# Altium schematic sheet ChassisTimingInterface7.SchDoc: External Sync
size B; Author: M. Pirello; Organization: LIGO Laboratory; Address1: California Institute of Technology; Address2: Massachusetts Institute of Technology; Address3: National Science Foundation; Address4: Australia 2086; DocumentNumber: 8; SheetNumber: 8; SheetTotal: 12; Size: B
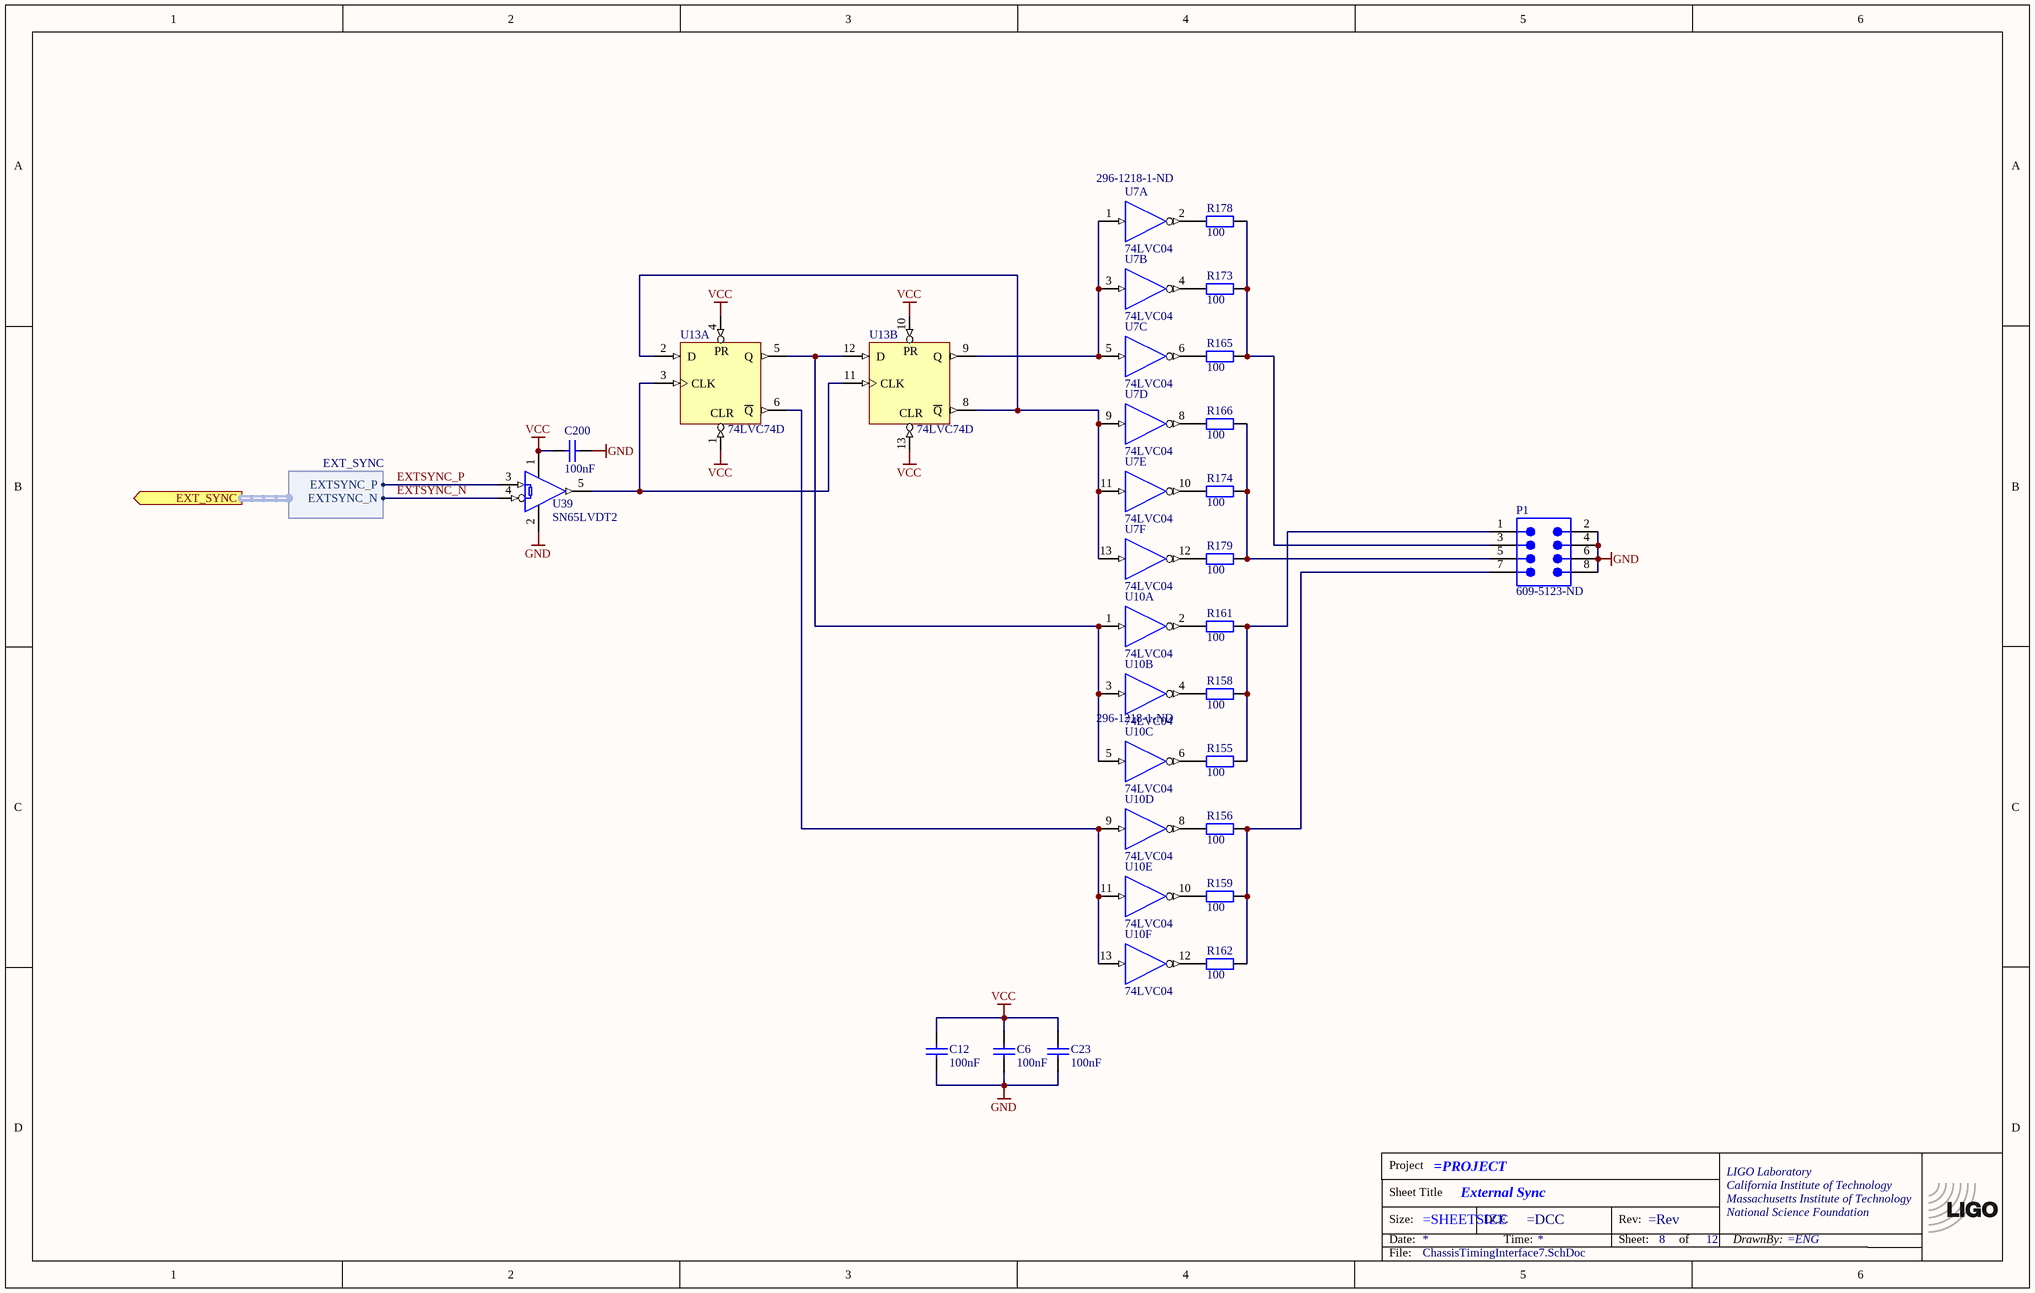
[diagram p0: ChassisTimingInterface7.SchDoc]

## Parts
*?  TitleBlock  (value not drawn)  (graphical)
?  (no value)  (no BOM)
C6  100nF  [CC1005-0402]
C12  100nF  [CC1005-0402]
C23  100nF  [CC1005-0402]
C200  100nF  [CC1005-0402]
P1  609-5123-ND  [9181089621]
R155  100  [CR1608-0603]
R156  100  [CR1608-0603]
R158  100  [CR1608-0603]
R159  100  [CR1608-0603]
R161  100  [CR1608-0603]
R162  100  [CR1608-0603]
R165  100  [CR1608-0603]
R166  100  [CR1608-0603]
R173  100  [CR1608-0603]
R174  100  [CR1608-0603]
R178  100  [CR1608-0603]
R179  100  [CR1608-0603]
U7  74LVC04  Supplier Part Number 1: 296-1218-1-ND  [TSSOP14]  (parts A,B,C,D,E,F of 6)
U10  74LVC04  [TSSOP14]  (parts A,B,C,D,E,F of 6)
U13  74LVC74D  [TSSOP14]  (parts A,B of 2)
U39  SN65LVDT2  [SO-G5/E2.4]

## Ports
EXT_SYNC (out, harness EXT_SYNC)

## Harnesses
EXT_SYNC: EXTSYNC_N, EXTSYNC_P

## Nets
GND: C6.2 C12.2 C23.2 C200.1 P1.2 P1.4 P1.6 P1.8 U7.7(GND) U10.7(GND) U13.7(GND) U39.2(GND)
VCC: C6.1 C12.1 C23.1 C200.2 U7.14(VCC) U10.14(VCC) U13.1(CLR) U13.4(PR) U13.10(PR) U13.13(CLR) U13.14(VCC) U39.1(VCC)
EXTSYNC_N: U39.4(B) ; port EXT_SYNC.EXTSYNC_N
EXTSYNC_P: U39.3(A) ; port EXT_SYNC.EXTSYNC_P
NetP1_1: P1.1 R155.2 R158.2 R161.2
NetP1_3: P1.3 R165.2 R173.2 R178.2
NetP1_5: P1.5 R166.2 R174.2 R179.2
NetP1_7: P1.7 R156.2 R159.2 R162.2
NetR155_1: R155.1 U10.6(Y)
NetR156_1: R156.1 U10.8(Y)
NetR158_1: R158.1 U10.4(Y)
NetR159_1: R159.1 U10.10(Y)
NetR161_1: R161.1 U10.2(Y)
NetR162_1: R162.1 U10.12(Y)
NetR165_1: R165.1 U7.6(Y)
NetR166_1: R166.1 U7.8(Y)
NetR173_1: R173.1 U7.4(Y)
NetR174_1: R174.1 U7.10(Y)
NetR178_1: R178.1 U7.2(Y)
NetR179_1: R179.1 U7.12(Y)
NetU7_1: U7.1(A) U7.3(A) U7.5(A) U13.9(Q)
NetU7_9: U7.9(A) U7.11(A) U7.13(A) U13.2(D) U13.8(~{Q})
NetU10_1: U10.1(A) U10.3(A) U10.5(A) U13.5(Q) U13.12(D)
NetU10_9: U10.9(A) U10.11(A) U10.13(A) U13.6(~{Q})
NetU13_3: U13.3(CLK) U13.11(CLK) U39.5(R)

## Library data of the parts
? = LIGO_logo: LIGO logo
C6 C12 C23 C200 = ChipCap: C0402 0.1uF; Part Number: 1276-6720-1-ND; Tolerance: 10%
P1 = 09 18 108 9621: Flat Cable Connector (IDC), PCB Transition Connector, 2 Rows, Solder Pin, 8 Contacts
R155 R156 R158 R159 R161 R162 R165 R166 R173 R174 R178 R179 = ChipRes1: R0603 100; Part Number: RR08P100DCT-ND; Tolerance: 0.1%
U7 = SN74AHCT04D: Hex Inverter
U10 = SN74AHCT04D: Hex Inverter; Part Number: 296-1218-1-ND
U13 = 74F74PC: Dual D-Type Positive Edge-Triggered Flip-Flop; Part Number: 296-1240-5-ND
U39 = SN65LVDT2DBV: Single LVDS Receiver with 100 Ohm termination; Part Number: 296-6896-1-ND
